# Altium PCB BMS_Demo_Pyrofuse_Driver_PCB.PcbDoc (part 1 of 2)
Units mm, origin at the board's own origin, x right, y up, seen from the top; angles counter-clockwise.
Board outline 130 x 44 mm, 2 copper layers (Top Layer, Bottom Layer), stack 1.575 mm thick; 66 components, 31 nets, 200 pads, 139 vias.
Unrouted connection lines stored in the file: 5.
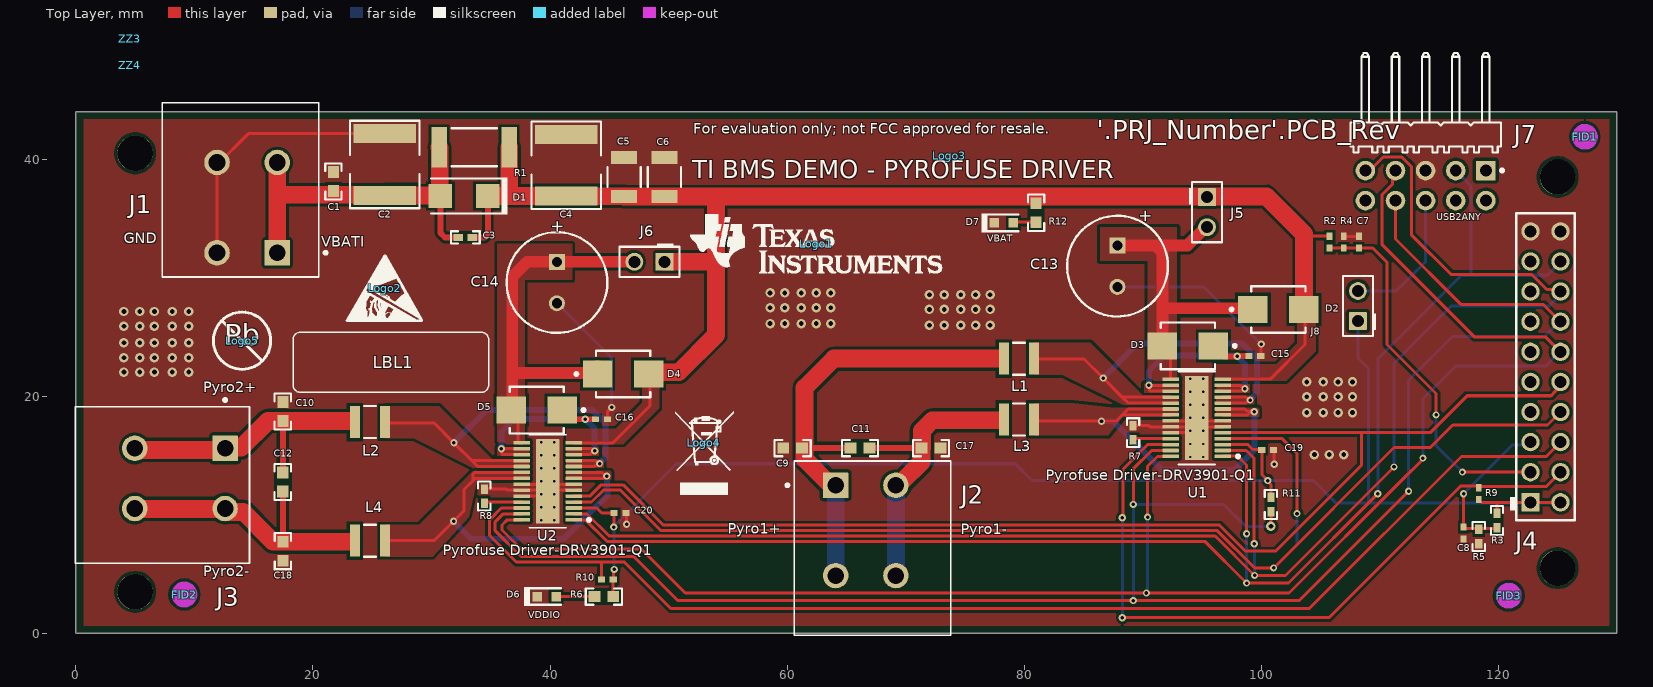
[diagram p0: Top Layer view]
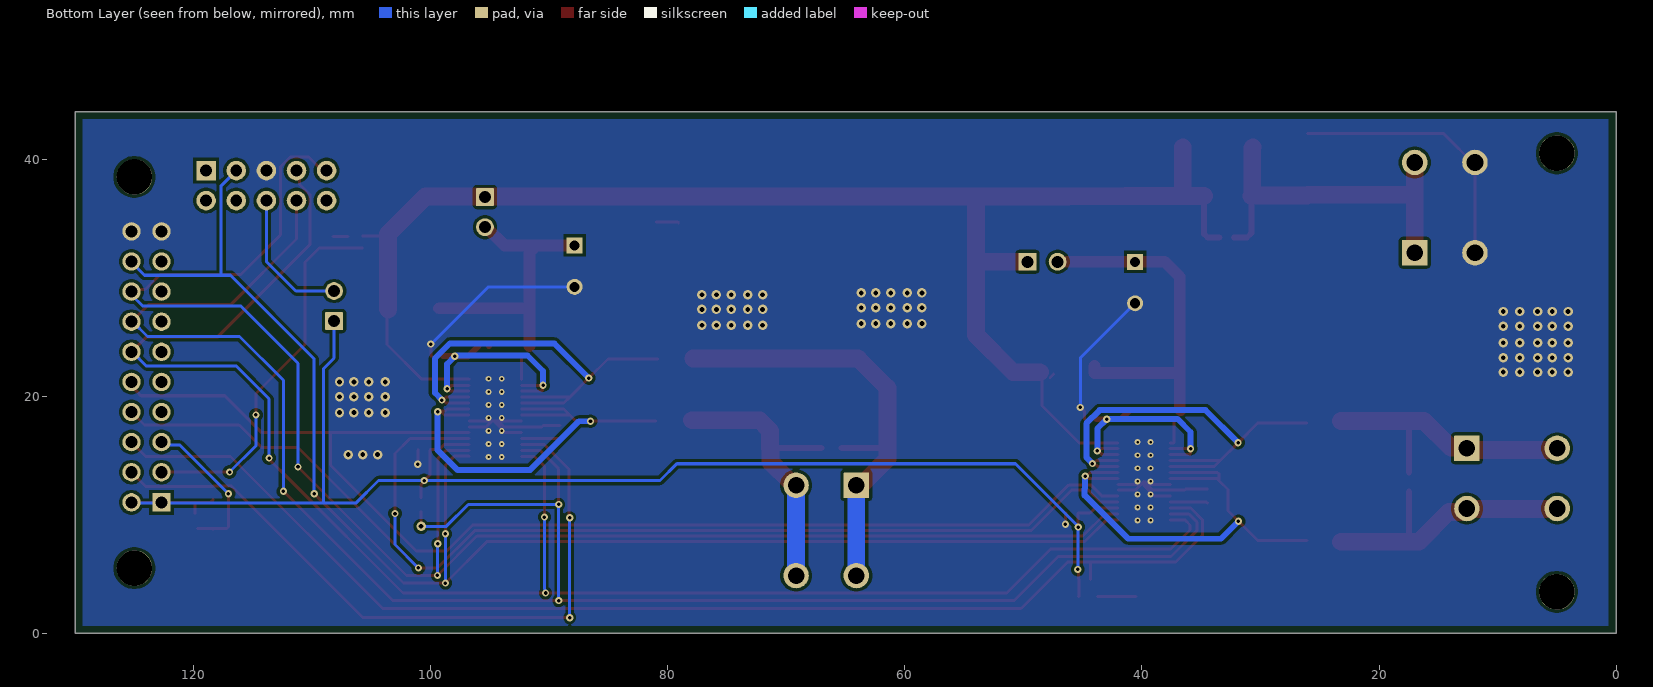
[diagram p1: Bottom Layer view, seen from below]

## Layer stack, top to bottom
Top Solder: solder mask 0.0102, Solder Resist, Dk 3.5
Top Layer: signal copper 0.0356
Dielectric1: core 1.5037, FR-4 High Tg, Dk 4.8
Bottom Layer: signal copper 0.0356
Bottom Solder: solder mask 0.0102, Solder Resist, Dk 3.5

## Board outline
0,0 130,0 130,44 0,44

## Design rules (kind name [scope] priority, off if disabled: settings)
AcuteAngle [All] p1: minimum=4.50000000000000E+0001 checktracksonly=FALSE
AssemblyTestPointUsage [All] p1: valid=2
BoardOutlineClearance BoardOutlineClearance_MountingHoles [OnCopper and InComponentClass('Mounting Holes')] p1: gap=1 ignorepadtopadclearanceinfootprint=FALSE
BoardOutlineClearance BoardOutlineClearance_Poly [OnCopper and IsPoly] p2: gap=0.635 ignorepadtopadclearanceinfootprint=FALSE
BoardOutlineClearance [OnCopper and Not InComponentClass('Logo') and not InComponentClass('FiducialMark') and not InRegion(1000,500,4000,800) and not InPoly] p3: gap=1.016 ignorepadtopadclearanceinfootprint=FALSE
Clearance Clearance_Keepouts [((IsTrack Or IsArc) And Not InPoly) And IsFree and IsKeepOut vs ((IsTrack Or IsArc) And Not InPoly) And IsFree and IsKeepOut] p1: gap=0 ignorepadtopadclearanceinfootprint=FALSE
Clearance Clearance_Poly [InPolygon] p2: gap=0.254 ignorepadtopadclearanceinfootprint=TRUE
Clearance Clearance_FiducialMark [IsKeepOut and InComponentClass('FiducialMark') vs IsPad and InComponentClass('FiducialMark')] p3: gap=0 ignorepadtopadclearanceinfootprint=FALSE
Clearance [All] p4: gap=0.2 ignorepadtopadclearanceinfootprint=TRUE
ComponentClearance ComponentClearance_MountingHoles_FiducialMarks [InComponentClass('Mounting Holes') vs InComponentClass('FiducialMark')] p1: gap=1.27 collisioncheckmode=3 verticalgap=0.254 showdistances=FALSE
ComponentClearance ComponentClearance_Shunt [InComponentClass('Header') vs InComponentClass('Shunt')] p2: gap=0 collisioncheckmode=3 verticalgap=0 showdistances=FALSE
ComponentClearance ComponentClearance_Logo [InComponentClass('Logo')] p3: gap=0.762 collisioncheckmode=3 verticalgap=0.254 showdistances=FALSE
ComponentClearance ComponentClearance_ScrewToNut [(HasFootprint('NY PMS 440 0025 PH')) vs (HasFootprint('Keystone_1902C'))] p4: gap=0.127 collisioncheckmode=3 verticalgap=0.254 showdistances=FALSE
ComponentClearance ComponentClearance_MountingHoles [InComponentClass('Mounting Holes')] p5: gap=2.54 collisioncheckmode=3 verticalgap=2540 showdistances=FALSE
ComponentClearance ComponentClearance_SmallPassives [HasFootprint('0201*') or HasFootprint('0402*') or HasFootprint('0508') or HasFootprint('0603*') or HasFootprint('0612') or HasFootprint('0805*') or HasFootprint('0815*') or HasFootprint('0830*') or HasFootprint('1206*') or HasFootprint('1210*') or HasFootprint('1808*') or HasFootprint('1812*') or HasFootprint('1825*') or HasFootprint('2010*') or HasFootprint('2220*') or HasFootprint('2225*') or HasFootprint('2512*') or HasFootprint('2728*') or HasFootprint('3518*') vs HasFootprint('0201*') or HasFootprint('0402*') or HasFootprint('0508') or HasFootprint('0603*') or HasFootprint('0612') or HasFootprint('0805*') or HasFootprint('0815*') or HasFootprint('0830*') or HasFootprint('1206*') or HasFootprint('1210*') or HasFootprint('1808*') or HasFootprint('1812*') or HasFootprint('1825*') or HasFootprint('2010*') or HasFootprint('2220*') or HasFootprint('2225*') or HasFootprint('2512*') or HasFootprint('2728*') or HasFootprint('3518*')] p6: gap=0.38 collisioncheckmode=3 verticalgap=0.254 showdistances=FALSE
ComponentClearance ComponentClearance_THtoSMT [IsThruComponent vs IsSMTComponent] p7: gap=0.762 collisioncheckmode=3 verticalgap=0.762 showdistances=FALSE
ComponentClearance ComponentClearance_THtoTH [IsThruComponent vs IsThruComponent] p8: gap=0.508 collisioncheckmode=3 verticalgap=0.762 showdistances=FALSE
ComponentClearance [All] p9: gap=0.508 collisioncheckmode=3 verticalgap=0.254 showdistances=FALSE
DiffPairsRouting [All] p1: maxlimit=2.54 minlimit=0.254 mostfreqgap=0.254 toplayer_minwidth=0.381 toplayer_maxwidth=0.381 toplayer_prefwidth=0.381 bottomlayer_minwidth=0.381 bottomlayer_maxwidth=0.381 bottomlayer_prefwidth=0.381 maxuncoupledlength=25.4
FabricationTestPointUsage TestPointUsage [All] p1: valid=2 allowmultiple=FALSE
FabricationTestpoint Testpoint [All] p1: side=3 testpointundercomponent=TRUE minsize=1.016 maxsize=2.54 preferedsize=1.524 minholesize=0 maxholesize=1.016 preferedholesize=0.813 testpointgrid=0.025 allowsidetop=TRUE allowsidebottom=TRUE usegrid=TRUE gridtolerance=0
FanoutControl Fanout_LCC [IsLCC] p1: bgadir=Out bgaviamode=Centered fanoutstyle=Auto fanoutdirection=Alternating viagrid=0.025 // Fanout_LCC (Default Rule)
FanoutControl Fanout_BGA [IsBGA] p2: bgadir=Out bgaviamode=Centered fanoutstyle=Auto fanoutdirection=Alternating viagrid=0.025 // Fanout_BGA (Default Rule)
FanoutControl Fanout_Default [All] p4: bgadir=Out bgaviamode=Centered fanoutstyle=Auto fanoutdirection=Alternating viagrid=0.025 // Fanout_Default (Default Rule)
FanoutControl Fanout_Small [(CompPinCount < 5)] p5: bgadir=Out bgaviamode=Centered fanoutstyle=Auto fanoutdirection=OutThenIn viagrid=0.025 // Fanout_Small (Default Rule)
HoleSize [All] p1: absolutevalues=TRUE maxlimit=6.375 minlimit=0.2 maxpercent=80.000 minpercent=20.000
MinimumAnnularRing MinimumAnnularRing_ThermalPadVias [IsVia and InAnyComponent] p1: minimumring=0.15
MinimumAnnularRing [All] p2: minimumring=0.1
MinimumSolderMaskSliver MinimumSolderMaskSliver_Logo [InComponentClass('Logo') vs InComponentClass('Logo')] p1: minsoldermaskwidth=0.018
MinimumSolderMaskSliver [All] p2: minsoldermaskwidth=0.1
PlaneConnect [All] p1: planeconnectstyle=Relief reliefexpansion=0.254 reliefentries=4 reliefconductorwidth=0.254 reliefairgap=0.254
PolygonConnect [All] p1: connectstyle=Direct reliefconductorwidth=0.254 reliefentries=4 polygonreliefangle="90 Angle" airgapwidth=0.254
RoutingVias ThermalPadVias [IsVia and InAnyComponent] p1: holewidth=0.2 width=0.5 viastyle="Through Hole" minholewidth=0.2 minwidth=0.5 maxholewidth=0.33 maxwidth=0.6
RoutingVias [All] p2: holewidth=0.406 width=0.864 viastyle="Through Hole" minholewidth=0.1 minwidth=0.61 maxholewidth=1.016 maxwidth=1.651
SilkToBoardRegionClearance [Not ((IsComment or IsDesignator) And (Hide <> 'False')) and not InRegion(1000,500,4000,800)] p1:
SilkToSilkClearance SilkToSilkClearance_Pb-FreeLogo [(HasFootprint('Pb-Free_Overlay_Medium') OR HasFootprint('Pb-Free_Overlay_Small')) vs (HasFootprint('Pb-Free_Overlay_Medium') OR HasFootprint('Pb-Free_Overlay_Small'))] p1: silktosilkclearance=0
SilkToSilkClearance [All] p2: silktosilkclearance=0.1
SilkToSolderMaskClearance SilkToComponentPadClearance [(IsPad or IsFill or IsRegion) and InAnycomponent] p1: minsilkscreentomaskgap=0.127 clearancetoexposedcopper=TRUE
SilkToSolderMaskClearance "Silk to Solder Mask Opening" [All] p2: minsilkscreentomaskgap=0.1 clearancetoexposedcopper=FALSE
SolderMaskExpansion [All] p1: expansion=0.05 istentingtop=FALSE
UnRoutedNet [All] p1: checkbadconnections=TRUE
Width [All] p1: maxlimit=2.54 minlimit=0.152 preferedwidth=0.254 checkconnectedcopper=TRUE
14 further rules are at their usual default settings.

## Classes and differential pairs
component class Header: J5 J6 J7 J8
component class BMS_Demo_Pyrofuse_Driver_Schematic: C1 C2 C3 C4 C5 C6 C7 C8 C9 C10 C11 C12 C13 C14 C15 C16 C17 C18 C19 C20 D1 D2 D3 D4 D5 D6 D7 J2 J3 J4 J5 J6 J7 J8 L1 L2 L3 L4 R1 R2 R3 R4 R5 R6 R7 R8 R9 R10 R11 R12 U1 U2
component class Label: LBL1
component class AssemblyNote: ZZ1 ZZ2 ZZ3 ZZ4
component class FiducialMark: FID1 FID2 FID3
component class BMS_Demo_Pyrufose_Driver_Hardware: FID1 FID2 FID3 LBL1 Logo1 Logo2 Logo3 Logo4 Logo5 ZZ1 ZZ2 ZZ3 ZZ4
component class Logo: Logo1

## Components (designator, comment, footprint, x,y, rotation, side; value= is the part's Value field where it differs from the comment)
C1 "CGA3E2X7R2A472K080AA" 0603 21.725,38.125 r90 top value=4700pF
C2 "CGA9P3X7S2A156M250KB" 2220_280 26.05,39.55 r90 top value=15uF
C3 "GRM1555C1H102JA01D" 0402 32.85,33.4 r180 top value=1000pF
C4 "CGA9P3X7S2A156M250KB" 2220_280 41.363,39.5 r90 top value=15uF
C5 "CGA6P3X7S1H106K250AB" 1210_280 46.25,38.5 r90 top value=10uF
C6 "CGA6P3X7S1H106K250AB" 1210_280 49.65,38.5 r90 top value=10uF
C7 "GRM155R71H471KA01D" 0402L 108.232,32.995 r90 top value=470pF
C8 "GRM155R71H471KA01D" 0402L 117.066,8.474 r270 top value=470pF
C9 "CGA3E2X7R1H473K080AA" 0603 60.471,15.628 r180 top value=0.047uF
C10 "CGA3E2X7R1H473K080AA" 0603 17.463,18.717 r90 top value=0.047uF
C11 "CGA3E2X7R1H473K080AA" 0603 66.146,15.628 r0 top value=0.047uF
C12 "CGA3E2X7R1H473K080AA" 0603 17.462,12.775 r270 top value=0.047uF
C13 "ELXZ500ELL101MH12D" Chemi-Con_800x1200 87.866,30.982 r270 top value=100uF
C14 "ELXZ500ELL101MH12D" Chemi-Con_800x1200 40.583,29.594 r270 top value=100uF
C15 "C1005X7R1H104K050BE" 0402L 99.458,23.384 r0 top value=0.1uF
C16 "C1005X7R1H104K050BE" 0402L 44.337,18.063 r0 top value=0.1uF
C17 "CGA3E2X7R1H473K080AA" 0603 72.146,15.628 r0 top value=0.047uF
C18 "CGA3E2X7R1H473K080AA" 0603 17.463,6.925 r270 top value=0.047uF
C19 "C1005X7R1H104K050BE" 0402L 100.543,15.481 r180 top value=0.1uF
C20 "C1005X7R1H104K050BE" 0402L 45.91,10.146 r180 top value=0.1uF
D1 "RB058L-60TE25" SMA 32.75,36.9 r180 top value=60V
D2 "S1AB-13-F" FP-SMB-MFG 101.443,27.321 r0 top
D3 "S1AB-13-F" FP-SMB-MFG 93.813,24.247 r180 top
D4 "S1AB-13-F" FP-SMB-MFG 46.168,21.874 r0 top
D5 "S1AB-13-F" FP-SMB-MFG 38.877,18.833 r180 top
D6 "150060VS75000" WL-SMCW_GREEN 39.714,3.099 r0 top value=Green
D7 "150060VS75000" WL-SMCW_GREEN 78.288,34.629 r0 top value=Green
FID1 "Fiducial" Fiducial10-20 127.305,41.885 r0 top
FID2 "Fiducial" Fiducial10-20 9.15,3.275 r0 top
FID3 "Fiducial" Fiducial10-20 120.875,3.175 r0 top
J1 "KF142R-5.08-2P" FP-KF142R-5.08-2P_HDR2-MFG 13.887,37.404 r180 top
J2 "KF142R-5.08-2P" FP-KF142R-5.08-2P_HDR2-MFG 67.197,7.19 r0 top
J3 "KF142R-5.08-2P" FP-KF142R-5.08-2P_HDR2-MFG 7.287,12.507 r270 top
J4 "SSQ-110-03-T-D" Samtec_SSQ-110-03-x-D 123.98,22.48 r90 top
J5 "PEC02SAAN" CONN_PEC02SAAN 95.428,35.535 r270 top
J6 "PEC02SAAN" CONN_PEC02SAAN 48.387,31.344 r180 top
J7 "TSW-105-08-G-D-RA" Samtec_TSW-105-08-G-D-RA 113.868,37.77 r180 top
J8 "PEC02SAAN" CONN_PEC02SAAN 108.153,27.608 r90 top
L1 "CBC3225T6R8MR" FP-CB3225-MFG 79.563,23.175 r180 top
L2 "CBC3225T6R8MR" FP-CB3225-MFG 24.813,17.825 r180 top
L3 "CBC3225T6R8MR" FP-CB3225-MFG 79.563,18.042 r180 top
L4 "CBC3225T6R8MR" FP-CB3225-MFG 24.813,7.825 r180 top
LBL1 "THT-14-423-10" Label_650x200 26.574,22.868 r0 top
Logo1 "Texas Instruments" TI_Stacked_Overlay_Small 62.456,32.868 r0 top
Logo2 "ESD Susceptible" ESD_Overlay_Medium 26.05,29.1 r0 top
Logo3 "FCC disclaimer" FCC_disclaimer 73.679,40.3 r0 top
Logo4 "WEEE logo" WEEE_Minimum 52.987,16.075 r0 top
Logo5 "Pb-Free Symbol" Pb-Free_Overlay_Medium 14.021,24.689 r0 top
R1 "CRCW25120000Z0EG" 2512 33.6,41.005 r0 top value=0
R2 "RC0402FR-0715KL" 0402L 105.768,32.995 r90 top value=15.0k
R3 "CRCW040210K0JNED" 0402 119.888,9.525 r90 top value=10k
R4 "RC0402FR-071KL" 0402L 106.962,32.995 r270 top value=1.00k
R5 "CRCW040210K0JNED" 0402 118.351,8.174 r90 top value=10k
R6 "CRCW06033K30JNEA" 0603 44.539,3.099 r0 top value=3.3k
R7 "CRCW040210K0FKED" 0402 89.19,16.925 r270 top value=10.0k
R8 "CRCW040210K0FKED" 0402 34.457,11.575 r270 top value=10.0k
R9 "CRCW04025K60JNED" 0402L 118.351,11.779 r270 top value=5.6k
R10 "CRCW040212K0JNED" 0402L 44.83,4.529 r0 top value=12k
R11 "CRCW040210K0FKED" 0402 100.813,10.876 r90 top value=10.0k
R12 "CRCW06038K20JNEA" 0603 81.004,35.482 r90 top value=8.2k
U1 "DRV3901QDGQRQ1" DGQ0028A-MFG 94.563,18.175 r180 top
U2 "DRV3901QDGQRQ1" DGQ0028A-MFG 39.813,12.825 r180 top
ZZ1 "This Assembly Note is for PCB labels only" AssemblyNoteLabel 4.524,55.175 r0 top
ZZ2 "These assemblies are ESD sensitive, ESD precautions shall be observed." AssemblyNote 4.524,52.409 r0 top
ZZ3 "These assemblies must be clean and free from flux and all contaminants. Use of no clean flux is not acceptable." AssemblyNote 4.524,50.16 r0 top
ZZ4 "These assemblies must comply with workmanship standards IPC-A-610 Class 2, unless otherwise specified." AssemblyNote 4.524,47.911 r0 top

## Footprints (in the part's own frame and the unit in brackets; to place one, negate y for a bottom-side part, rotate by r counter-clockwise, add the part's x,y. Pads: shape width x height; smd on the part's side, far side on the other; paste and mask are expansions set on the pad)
0402 [mm] "0402 from SM-752 data"
  rect 0.8x0.6 smd: 1(-0.6,0) 2(0.6,0)
  silkscreen extent -1.22,-0.52 1.22,0.52, body extent -0.55,-0.3 0.55,0.3, height 0.6
0402L [mm] "0402 from SM-752 data"
  rect 0.6x0.5 smd: 1(-0.5,0) 2(0.5,0)
  body extent -0.55,-0.3 0.55,0.3, height 0.6
0603 [mm] "0603 from SM-752 data"
  rect 1x0.95 smd: 1(-0.8,0) 2(0.8,0)
  silkscreen extent -1.52,-0.69 1.52,0.69, body extent -0.87,-0.47 0.87,0.47, height 1
1210_280 [mm] "SMD, 2-Leads, Body 3.6x2.8mm, Height 2.8mm"
  rect 1.1x2.2 smd: 1(-1.65,0) 2(1.65,0)
  silkscreen extent -0.84,-1.4 0.84,1.4, body extent -1.8,-1.4 1.8,1.4, height 2.8
2220_280 [mm] "Chip Capacitor, Body 5.7x5.0mm, IPC Medium Density"
  rect 1.6x5.3 smd: 1(-2.6,0) 2(2.6,0)
  silkscreen extent -3.69,-2.94 3.69,2.94, body extent -2.95,-2.62 2.95,2.62, height 2.8
2512 [mm] "Chip Resistor, Body 6.3x3.2mm, IPC Medium Density"
  rect 1.3x3.4 smd: 1(-2.95,0) 2(2.95,0)
  silkscreen extent -1.9,-1.6 1.9,1.6, body extent -3.22,-1.67 3.22,1.67, height 0.71
AssemblyNote [mm] "Assembly Note"
AssemblyNoteLabel [mm] "Assembly Note for PCB Labels"
Chemi-Con_800x1200 [mm] "TH, 2-Leads, Dia 8mm, Pin Spacing 3.5mm"
  rect 1.35x1.35 hole 0.85: 1(-1.75,0)
  round 1.35 hole 0.85: 2(1.75,0)
  silkscreen extent -4.25,-4.25 4.25,4.25, body extent -4.25,-4.25 4.26,4.25, height 13.51
CONN_PEC02SAAN [mm] "SULLINS"
  rrect7% 1.5x1.5 hole 1.016: 1(-1.27,0)
  round 1.5 hole 1.016: 2(1.27,0)
  silkscreen extent -2.54,-1.52 2.54,1.27, body extent -2.54,-1.27 2.54,1.27, height 8.38
DGQ0028A-MFG [mm]
  rrect33% 1.4x0.3 smd paste+0 mask+0: 1(-2.2,3.25) 2(-2.2,2.75) 3(-2.2,2.25) 4(-2.2,1.75) 5(-2.2,1.25) 6(-2.2,0.75) 7(-2.2,0.25) 8(-2.2,-0.25) 9(-2.2,-0.75) 10(-2.2,-1.25) 11(-2.2,-1.75) 12(-2.2,-2.25) 13(-2.2,-2.75) 14(-2.2,-3.25) 15(2.2,-3.25) 16(2.2,-2.75) 17(2.2,-2.25) 18(2.2,-1.75) 19(2.2,-1.25) 20(2.2,-0.75) 21(2.2,-0.25) 22(2.2,0.25) 23(2.2,0.75) 24(2.2,1.25) 25(2.2,1.75) 26(2.2,2.25) 27(2.2,2.75) 28(2.2,3.25)
  rrect5% 2x7.1 smd paste-1000 mask-1000: 29(0,0)
  silkscreen extent -3.6,-3.92 1.55,3.92, body extent -3,-3.85 3,3.85, height 0.25
ESD_Overlay_Medium [mm]
  silkscreen extent -3.22,-2.77 3.17,2.8
FCC_disclaimer [mm]
Fiducial10-20 [mm]
  round 1 smd mask+0.5: 1(0,0)
  Top Layer keep-out circle w1.178: c0,0 r0.5
FP-CB3225-MFG [mm]
  rect 0.85x2.7 smd paste+0 mask+0: 1(-1.275,0) 2(1.275,0)
  silkscreen extent -0.48,-1.35 0.48,1.35, body extent -1.8,-1.45 1.8,1.45, height 0.25
FP-KF142R-5.08-2P_HDR2-MFG [mm]
  rrect5% 2.15x2.15 hole 1.4 paste-1000 mask+0: 1(-3.1,5.3)
  round 2.15 hole 1.4 paste-1000 mask+0: 1(-3.1,-2.32) 2(1.98,5.3) 2(1.98,-2.32)
  silkscreen extent -7.3,-7.35 6.6,7.35, body extent -6.7,-7.45 6.7,7.45, height 0.25
FP-SMB-MFG [mm]
  rect 2.5x2.3 smd paste+0 mask+0: 1(-2.15,0) 2(2.15,0)
  silkscreen extent -4.07,-1.97 2.28,1.97, body extent -3.5,-2.07 3.5,2.07, height 0.25
Label_650x200 [mil] "Thermal Transfer Label"
  round 1 on Mech13: 0(0,0)
  silkscreen extent -325,-100 325,100, body extent -325,-100 325,100, height 1
Pb-Free_Overlay_Medium [mm]
  silkscreen extent -2.41,-2.41 2.41,2.41
Samtec_SSQ-110-03-x-D [mm] "Receptacle, 2.54mm, 10x2, TH"
  rect 1.55x1.55 hole 1.02: 1(-11.43,1.27)
  round 1.55 hole 1.02: 2(-11.43,-1.27) 3(-8.89,1.27) 4(-8.89,-1.27) 5(-6.35,1.27) 6(-6.35,-1.27) 7(-3.81,1.27) 8(-3.81,-1.27) 9(-1.27,1.27) 10(-1.27,-1.27) 11(1.27,1.27) 12(1.27,-1.27) 13(3.81,1.27) 14(3.81,-1.27) 15(6.35,1.27) 16(6.35,-1.27) 17(8.89,1.27) 18(8.89,-1.27) 19(11.43,1.27) 20(11.43,-1.27)
  silkscreen extent -12.95,-2.48 12.95,3, body extent -12.95,-2.48 12.95,2.48, height 8.51
Samtec_TSW-105-08-G-D-RA [mm] "Samtec Right Angle Header"
  rrect6% 1.65x1.65 / inner rect 1.65x1.65 / far side rect 1.65x1.65 hole 1: 1(-5.08,-1.27)
  round 1.65 hole 1: 2(-5.08,1.27) 3(-2.54,-1.27) 4(-2.54,1.27) 5(0,-1.27) 6(0,1.27) 7(2.54,-1.27) 8(2.54,1.27) 9(5.08,-1.27) 10(5.08,1.27)
  silkscreen extent -6.58,-11.18 6.35,-1.16, body extent -6.35,-11.18 6.35,1.59, height 5.64
SMA [mm] "Molded Diode, 2-Leads, Body 4.3x2.6mm, IPC Medium Density, based on OnSemi component dimensions and land pattern"
  rect 2x2 smd: 1(-2,0) 2(2,0)
  silkscreen extent -3.66,-1.57 2.79,1.57, body extent -2.6,-1.3 2.6,1.3, height 2.42
TI_Stacked_Overlay_Small [mm]
  silkscreen extent -10.63,-2.49 10.63,2.49
WEEE_Minimum [mm] "WEEElie bin"
  silkscreen extent -2.42,-4.38 2.52,2.65
WL-SMCW_GREEN [mm] "WURTH"
  rect 0.8x0.8 smd: 1(-0.8,0) 2(0.8,0)
  silkscreen extent -1.9,-0.8 1.2,0.8, body extent -0.85,-0.45 0.85,0.45, height 0.8

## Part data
C1: library part CMP-0007088-4, "CAP, CERM, 4700 pF, 100 V, +/- 10%, X7R, AEC-Q200 Grade 1, 0603", Cap_Case=0603, Manufacturer=TDK, Supplier Part Number 1=445-5810-1-ND, TempCo=X7R, Tolerance_%=10%, Value1="0.469862 ohm", Value2=100V, ValueDisplayed=4700pF
C2 C4: library part CMP-0009420-2, "CAP, CERM, 15 uF, 100 V, +/- 20%, X7S, AEC-Q200 Grade 1, 2220", Cap_Case=2220_280, Manufacturer=TDK, Supplier Part Number 1=445-7948-1-ND, TempCo=X7S, Tolerance_%=20%, Value1="0.002642 ohm", Value2=100V, ValueDisplayed=15uF
C3: library part CMP-0006412-2, "CAP, CERM, 1000 pF, 50 V, +/- 5%, C0G/NP0, 0402", Cap_Case=0402, Manufacturer=MuRata, Supplier Part Number 1=490-3244-1-ND, TempCo=C0G/NP0, Tolerance_%=5%, Value1=Unknown, Value2=50V, ValueDisplayed=1000pF
C5 C6: library part CMP-0009164-2, "CAP, CERM, 10 uF, 50 V, +/- 10%, X7S, AEC-Q200 Grade 1, 1210", Cap_Case=1210_280, Manufacturer=TDK, Supplier Part Number 1=445-7004-1-ND, TempCo=X7S, Tolerance_%=10%, Value1="0.002827 ohm", Value2=50V, ValueDisplayed=10uF
C7 C8: library part CMP-0006691-2, "CAP, CERM, 470 pF, 50 V, +/- 10%, X7R, 0402", Cap_Case=0402, Manufacturer=MuRata, Supplier Part Number 1=490-1300-1-ND, TempCo=X7R, Tolerance_%=10%, Value1=Unknown, Value2=50V, ValueDisplayed=470pF
C9 C10 C11 C12 C17 C18: library part CMP-0007079-4, "CAP, CERM, 0.047 uF, 50 V, +/- 10%, X7R, AEC-Q200 Grade 1, 0603", Cap_Case=0603, Manufacturer=TDK, Supplier Part Number 1=445-5664-1-ND, TempCo=X7R, Tolerance_%=10%, Value1="0.049007 ohm", Value2=50V, ValueDisplayed=0.047uF
C13 C14: library part CMP-0009893-2, "CAP, AL, 100 uF, 50 V, +/- 20%, AEC-Q200 Grade 2, TH", Cap_Case=8x12mm, Manufacturer=Chemi-Con, Supplier Part Number 1=565-2005-ND, Tolerance_%=20%, Value1=Unknown, Value2=50V, ValueDisplayed=100uF
C15 C16 C19 C20: library part CMP-0064946-2, "CAP, CERM, 0.1 uF, 50 V,+/- 10%, X7R, 0402", Cap_Case=0402, Manufacturer=TDK, Supplier Part Number 1=445-173610-1-ND, TempCo=X7R, Tolerance_%=10%, Value1=Unknown, Value2=50V, ValueDisplayed=0.1uF
D1: library part CMP-0028854-2, "Diode, Schottky, 60 V, 3 A, AEC-Q101, SMA", Manufacturer=Rohm, Value1=3A, Value2=0.64V
D2 D3 D4 D5: library part CMP-0586-00001-3, "DIODE GEN PURP 50V 1A SMB", Average Rectified Current=1A, Capacitance=10pF, Case/Package=SMB, Forward Voltage=1.1V, Max Operating Temperature=150°C, Max Repetitive Reverse Voltage (Vrrm)=50V, Max Surge Current=30A, Min Operating Temperature=-65°C, Package Quantity=3000, Peak Reverse Current=5uA
D6 D7: library part CMP-0002894-2, "LED, Green, SMD", Color=green, Manufacturer="Wurth Elektronik", Value1=W, Value2=2V
FID1 FID2 FID3: library part CMP-0077181-1, "Fiducial mark.  There is nothing to buy or mount.", Manufacturer=N/A
J1 J2 J3: library part CMP-0122691-1, "1.5 5.08mm 14~22 15A 2P 250V 2 Push-Pull,P=5.08mm Spring Clamp System Terminal Block ROHS", Current_A=10A, Manufacturer="Cixi Kefa Electronics", Operating Temperature Range="-40°C to +105°C", Voltage_V=300V
J4: library part CMP-0079854-1, "Receptacle, 2.54mm, 10x2, Tin, TH", Color=Black, Current_A=6.3A, Manufacturer=Samtec, Supplier Part Number 1=SAM1204-10-ND, Voltage_V=550V
J5 J6 J8: library part CMP-0002337-1, "Header, 100mil, 2x1, Tin, TH", Color=Black, Current_A=3A, Manufacturer="Sullins Connector Solutions", Supplier Part Number 1=S1012E-02-ND, Voltage_V=1.8kV
J7: library part CMP-0075472-2, "Header, 100mil, 5x2, Gold, R/A, TH", Color=Black, Current_A=6.3A, Manufacturer=Samtec, Supplier Part Number 1=SAM1037-05-ND, Voltage_V=550V
L1 L2 L3 L4: library part CMP-14484-000108-1, "SMD Inductors 6.8uH ±20% 0.94A 0.156Ω 1210", Case Code (Imperial)=1210, Case Code (Metric)=3225, Current Rating=940mA, DC Resistance (DCR)=156mR, Inductance=6.8uH, Max DC Current=950mA, Max Operating Temperature=105°C, Min Operating Temperature=-40°C, Package Quantity=1000, Resistor Type=Wirewound, Saturation Current=930mA, Self Resonant Frequency=50MHz, Test Frequency=100kHz, Tolerance=20%
LBL1: library part CMP-0003625-1, "Thermal Transfer Printable Labels, 0.650\" W x 0.200\" H - 10,000 per roll", Manufacturer=Brady, Supplier Part Number 1=97C5133
Logo1: library part CMP-0074838-1, "Texas Instrument Corporate Signature"
Logo2: library part CMP-0074840-1, "ESD Susceptible Symbol"
Logo3: library part CMP-0074847-1, "FCC_disclaimer"
Logo4: library part CMP-0074769-1
Logo5: library part CMP-0074839-1
R1: library part CMP-0015864-3, "RES, 0, 5%, 1 W, AEC-Q200 Grade 0, 2512", Manufacturer=Vishay-Dale, Power_W=1W, Supplier Part Number 1=541-0.0XCT-ND, TempCo=ppm/C, Tolerance_%=5%, Value_Code=0000, ValueDisplayed=0
R2: library part CMP-0078583-1, "RES, 15.0 k, 1%, 0.063 W, 0402", Manufacturer="Yageo America", Power_W=63mW, Supplier Part Number 1=311-15.0KLRCT-ND, TempCo="100 ppm/C", Tolerance_%=1%, Value2=0.063W, Value_Code=15k0, ValueDisplayed=15.0k
R3 R5: library part CMP-0026825-5, "RES, 10 k, 5%, 0.063 W, AEC-Q200 Grade 0, 0402", Manufacturer=Vishay-Dale, Power_W=63mW, Supplier Part Number 1=541-10KJCT-ND, TempCo="200 ppm/C", Tolerance_%=5%, Value2=0.063W, Value_Code=10k0, ValueDisplayed=10k
R4: library part CMP-0026725-1, "RES, 1.00 k, 1%, 0.0625 W, 0402", Manufacturer="Yageo America", Power_W=62.5mW, Supplier Part Number 1=311-1.00KLRCT-ND, TempCo="100 ppm/C", Tolerance_%=1%, Value2=0.0625W, Value_Code=1k00, ValueDisplayed=1.00k
R6: library part CMP-0025797-4, "RES, 3.3 k, 5%, 0.1 W, AEC-Q200 Grade 0, 0603", Manufacturer=Vishay-Dale, Power_W=100mW, Supplier Part Number 1=541-3.3KGCT-ND, TempCo="200 ppm/C", Tolerance_%=5%, Value2=0.1W, Value_Code=3k30, ValueDisplayed=3.3k
R7 R8 R11: library part CMP-0025958-3, "RES, 10.0 k, 1%, 0.063 W, AEC-Q200 Grade 0, 0402", Manufacturer=Vishay-Dale, Power_W=63mW, Supplier Part Number 1=541-10.0KLCT-ND, TempCo="100 ppm/C", Tolerance_%=1%, Value2=0.063W, Value_Code=10k0, ValueDisplayed=10.0k
R9: library part CMP-0026952-5, "RES, 5.6 k, 5%, 0.063 W, AEC-Q200 Grade 0, 0402", Manufacturer=Vishay-Dale, Power_W=63mW, Supplier Part Number 1=541-5.6KJCT-ND, TempCo="200 ppm/C", Tolerance_%=5%, Value2=0.063W, Value_Code=5k60, ValueDisplayed=5.6k
R10: library part CMP-0026834-3, "RES, 12 k, 5%, 0.063 W, AEC-Q200 Grade 0, 0402", Manufacturer=Vishay-Dale, Power_W=63mW, Supplier Part Number 1=541-12KJCT-ND, TempCo="200 ppm/C", Tolerance_%=5%, Value2=0.063W, Value_Code=12k0, ValueDisplayed=12k
R12: library part CMP-0025862-4, "RES, 8.2 k, 5%, 0.1 W, AEC-Q200 Grade 0, 0603", Manufacturer=Vishay-Dale, Power_W=100mW, Supplier Part Number 1=541-8.2KGCT-ND, TempCo="200 ppm/C", Tolerance_%=5%, Value2=0.1W, Value_Code=8k20, ValueDisplayed=8.2k
U1 U2: library part CMP-0095728-2, "1 Channel, 12-V Automotive Pyro-fuse Driver with Functional Safety", Manufacturer="Texas Instruments", Operating Temperature Range=to
ZZ1: library part CMP-0003616-3
ZZ2: library part CMP-0077236-1
ZZ3: library part CMP-0077237-1
ZZ4: library part CMP-0077238-1

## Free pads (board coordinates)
  round 3 hole 3: 1(5,3.5) 1(5,40.5) 1(125,5.5) 1(125,38.5)

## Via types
v1: diameter 0.8, hole 0.4, Top Layer to Bottom Layer, 71 vias
v2: diameter 0.61, hole 0.3, Top Layer to Bottom Layer, 40 vias
v3: diameter 0.5, hole 0.2, Top Layer to Bottom Layer, tented both sides, 28 vias

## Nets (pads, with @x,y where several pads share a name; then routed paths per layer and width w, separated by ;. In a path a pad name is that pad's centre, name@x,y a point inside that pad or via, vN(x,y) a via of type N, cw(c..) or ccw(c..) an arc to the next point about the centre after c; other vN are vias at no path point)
GND: C1.2 C2.2 C4.2 C5.2 C6.2 C7.2 C8.2 C9.2 C10.2 C13.2 C14.2 C15.2 C16.2 C17.2 C18.2 C19.1 C20.1 D6.1 D7.1 J1.2 J4.19 J4.20 J7.5 R4.1 R5.1 R7.1 R8.1 U1.6 U1.7 U1.22 U1.23 U1.24 U1.29 U2.6 U2.7 U2.22 U2.23 U2.24 U2.29 | length 83.6
  Top Layer w0.254: J1.2@11.907,31.893 11.907,39.513 14.544,42.15 C2.2@26.05,42.15 ; R8.1@34.457,12.175 36.307,12.175 36.407,12.075 U2.23@37.613,12.075 39.063,12.075 U2.29@39.563,12.575 ; U2.24@37.613,11.575 38.94,11.575 39.813,12.448 U2.29@39.813,12.825 ; U2.22@37.613,12.575 U2.29@39.563,12.575 ; U2.6@42.013,12.075 40.563,12.075 U2.29@40.063,12.575 ; U2.7@42.013,12.575 U2.29@40.063,12.575 ; C16.2@44.837,18.063 44.837,18.694 v2(45.198,19.055) ; C20.1@46.41,10.146 46.435,10.121 46.435,9.225 v2(46.46,9.2) ; R7.1@89.09,17.525 R7.1@89.19,17.525 90.525,17.525 90.625,17.425 U1.23@92.363,17.425 93.813,17.425 U1.29@94.313,17.925 ; U1.24@92.363,16.925 93.69,16.925 94.563,17.798 U1.29@94.563,17.925 ; U1.22@92.363,17.925 U1.29@94.313,17.925 ; U1.6@96.763,17.425 95.313,17.425 U1.29@94.813,17.925 ; U1.7@96.763,17.925 U1.29@94.813,17.925 ; C15.2@99.958,23.384 99.975,23.401 99.975,24.388 v2(99.993,24.405) ; C19.1@101.043,15.481 101.068,15.456 101.068,14.287 v2(101.093,14.262) ; R4.1@106.962,33.495 C7.2@108.232,33.495 ; J4.20@125.24,33.92 J4.20@125.25,33.91 ; U2.29@39.563,12.575 U2.29@39.813,12.825 ; U2.29@39.813,12.825 U2.29@40.063,12.575 ; U1.29@94.313,17.925 U1.29@94.563,17.925 ; U1.29@94.563,17.925 U1.29@94.813,17.925
  Bottom Layer w0.254: C14.2@40.314,28.12 45.198,23.235 v2(45.198,19.055) ; C13.2@87.866,29.232 95.137,29.232 v2@100.013,24.356
  other v1: 104.486,15.085 105.742,15.085 106.962,15.085 103.828,18.625 105.223,18.625 106.479,18.625 107.698,18.625 103.828,19.955 105.223,19.955 106.479,19.955 107.698,19.955 103.828,21.206 105.223,21.206 106.479,21.206 107.698,21.206 4.048,22.038 5.379,22.038 6.629,22.038 8.121,22.038 9.521,22.038 4.048,23.257 5.379,23.257 6.629,23.257 8.121,23.257 9.521,23.257 4.048,24.514 5.379,24.514 6.629,24.514 8.121,24.514 9.521,24.514 4.048,25.908 5.379,25.908 6.629,25.908 8.121,25.908 9.521,25.908 72.006,25.99 73.248,25.99 74.643,25.99 75.899,25.99 77.119,25.99 58.563,26.136 59.805,26.136 61.2,26.136 62.456,26.136 63.675,26.136 4.048,27.15 5.379,27.15 6.629,27.15 8.121,27.15 9.521,27.15 72.006,27.321 73.248,27.321 74.643,27.321 75.899,27.321 77.119,27.321 58.563,27.467 59.805,27.467 61.2,27.467 62.456,27.467 63.675,27.467 72.006,28.571 73.248,28.571 74.643,28.571 75.899,28.571 77.119,28.571 58.563,28.718 59.805,28.718 61.2,28.718 62.456,28.718 63.675,28.718
  other v3: 39.263,9.525 40.363,9.525 39.263,10.625 40.363,10.625 39.263,11.725 40.363,11.725 39.263,12.825 40.363,12.825 39.263,13.925 40.363,13.925 94.013,14.875 95.113,14.875 39.263,15.025 40.363,15.025 94.013,15.975 95.113,15.975 39.263,16.125 40.363,16.125 94.013,17.075 95.113,17.075 94.013,18.175 95.113,18.175 94.013,19.275 95.113,19.275 94.013,20.375 95.113,20.375 94.013,21.475 95.113,21.475
NetC13_1: C13.1 D2.1 D3.2 J5.2 U1.15 | length 26.6
  Top Layer w0.254: D3.2@92.328,23.425 92.363,23.39 U1.15@92.363,21.425
  Top Layer w1: C13.1@87.866,32.732 91.077,32.732 ; D3.2@91.663,24.247 91.663,27.419 ; J5.2@95.428,34.265 95.312,34.265 93.779,32.732 91.077,32.732 ; D2.1@99.293,27.419 91.663,27.419 ; 91.077,32.732 91.663,32.146 91.663,27.419
NetC14_1: C14.1 D4.1 D5.2 J6.2 U2.15 | length 32.1
  Top Layer w0.254: D5.2@37.303,18 37.303,16.098 37.326,16.075 U2.15@37.613,16.075
  Top Layer w1: D5.2@36.727,18.833 36.812,18.918 36.812,21.962 ; D4.1@44.018,22.552 44.018,21.962 36.812,21.962 ; J6.2@47.117,31.344 C14.1@40.583,31.344 38.077,31.344 36.812,30.078 36.812,21.962
NetC15_1: C15.1 D3.1 U1.12 U1.13 U1.16 U1.17 | length 23.4
  Top Layer w0.254: U1.17@92.363,20.425 90.674,20.425 90.593,20.506 90.593,20.857 v2(90.525,20.925) U1.16@92.363,20.925 ; U1.12@96.763,20.425 98.319,20.425 v2@98.529,20.635 ; U1.13@96.763,20.925 98.239,20.925 v2@98.529,20.635 ; v2(98.625,20.635) v2@98.529,20.635
  Top Layer w0.5: D3.1@95.088,24.247 D3.1@95.107,24.228 ; D3.1@95.963,24.247 96.845,23.366 v2(97.97,23.366) 97.989,23.384 C15.1@98.958,23.384
  Bottom Layer w0.5: v2(90.525,20.925) 90.525,22.125 91.842,23.442 v2@97.821,23.442 ; v2(97.97,23.366) 97.97,23.361 98.625,22.707 v2(98.625,20.635)
NetC16_1: C16.1 D5.1 U2.12 U2.13 U2.16 U2.17 | length 22.7
  Top Layer w0.254: U2.17@37.613,15.075 36.006,15.075 35.899,15.181 v2(35.899,15.575) U2.16@37.613,15.575 ; D5.1@40.152,18.833 D5.1@40.227,18.908 ; U2.12@42.013,15.075 43.357,15.075 v2@43.668,15.386 ; U2.13@42.013,15.575 43.479,15.575 v2@43.668,15.386 ; v2@43.715,15.386 v2@43.668,15.386 ; v2(43.764,15.386) v2@43.668,15.386
  Top Layer w0.5: D5.1@41.027,18.833 41.796,18.063 v2(42.98,18.063) C16.1@43.837,18.063
  Bottom Layer w0.5: v2(35.899,15.575) 35.899,16.989 36.985,18.075 42.968,18.075 v2(42.98,18.063) 43.764,17.279 v2(43.764,15.386)
NetD6_2: D6.2 R6.1 | length 3.2
  Top Layer w0.254: D6.2@40.514,3.099 R6.1@43.739,3.099
NetD7_2: D7.2 R12.1 | length 1.9
  Top Layer w0.254: D7.2@79.088,34.629 79.141,34.682 R12.1@81.004,34.682
NetL1_1: L1.1 U1.10 U1.11 U1.18 U1.19 | length 40.3
  Top Layer w0.254: L1.1@80.838,23.15 85.05,23.15 v2(86.662,21.538) 88.275,19.925 ; U1.19@92.363,19.425 88.775,19.425 88.275,19.925 ; U1.18@92.363,19.925 88.275,19.925 ; U1.10@96.763,19.425 98.247,19.425 98.71,19.425 v2@98.963,19.678 ; U1.11@96.763,19.925 98.716,19.925 v2@98.963,19.678 ; v2(99.059,19.678) v2@98.963,19.678
  Bottom Layer w0.5: v2(86.662,21.538) 89.575,24.45 98.391,24.45 99.643,23.198 99.643,20.292 99.059,19.708 v2(99.059,19.678)
NetL2_1: L2.1 U2.10 U2.11 U2.18 U2.19 | length 39.7
  Top Layer w0.254: L2.1@26.088,17.725 30.246,17.725 v2(31.887,16.084) 33.396,14.575 ; U2.19@37.613,14.075 33.896,14.075 33.396,14.575 ; U2.18@37.613,14.575 33.396,14.575 ; U2.10@42.013,14.075 43.753,14.075 43.858,14.18 43.946,14.18 v2@44.085,14.319 ; U2.11@42.013,14.575 43.829,14.575 v2@44.085,14.319 ; v2(44.181,14.319) v2@44.085,14.319
  Bottom Layer w0.5: v2(31.887,16.084) 34.635,18.833 43.567,18.833 44.688,17.711 44.688,14.856 44.181,14.349 v2(44.181,14.319)
NetL3_1: L3.1 U1.8 U1.9 U1.20 U1.21 | length 39.9
  Top Layer w0.254: L3.1@81.004,17.893 87.743,17.893 88.275,18.425 ; U1.21@92.363,18.425 88.275,18.425 ; U1.20@92.363,18.925 88.775,18.925 88.275,18.425 ; U1.8@96.763,18.425 98.837,18.425 99.043,18.631 99.349,18.631 v2(99.417,18.699) 99.349,18.767 98.762,18.767 98.605,18.925 U1.9@96.763,18.925
  Bottom Layer w0.5: v2(86.524,17.893) 87.502,17.893 91.603,13.792 97.761,13.792 99.417,15.449 v2(99.417,18.699)
NetL4_1: L4.1 U2.8 U2.9 U2.20 U2.21 | length 41.8
  Top Layer w0.254: L4.1@26.088,7.825 30.235,7.825 v2(31.86,9.45) 32.75,10.34 32.75,12.125 33.485,12.86 33.485,12.87 ; U2.21@37.613,13.075 37.59,13.052 33.667,13.052 33.485,12.87 ; U2.20@37.613,13.575 33.634,13.575 33.485,13.426 33.485,12.87 ; U2.8@42.013,13.075 44.497,13.075 v2@44.687,13.264 ; U2.9@42.013,13.575 44.376,13.575 v2@44.687,13.264 ; v2(44.783,13.264) v2@44.687,13.264
  Bottom Layer w0.5: v2(31.86,9.45) 33.33,7.98 41.171,7.98 ; 41.242,8.05 44.83,11.639 44.83,12.188 44.804,12.214 44.804,13.243 v2(44.783,13.264)
NetR7_2: R7.2 U1.25 | length 3.3
  Top Layer w0.254: R7.2@89.09,16.325 89.19,16.425 U1.25@92.363,16.425
NetR8_2: R8.2 U2.25 | length 3.2
  Top Layer w0.254: R8.2@34.457,10.975 34.557,11.075 U2.25@37.613,11.075
Pyro1+: C9.1 C11.1 J2.1 L1.2 | length 38.6
  Top Layer w0.5: C9.1@61.271,15.628 61.477,15.628 C11.1@65.346,15.628
  Top Layer w1.5: J2.1@64.097,12.49 64.001,12.586 63.599,12.586 61.477,14.708 61.477,15.628 61.477,20.72 63.932,23.175 L1.2@77.863,23.175
  Bottom Layer w1.5: J2.1@64.097,4.87 J2.1@64.097,12.49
